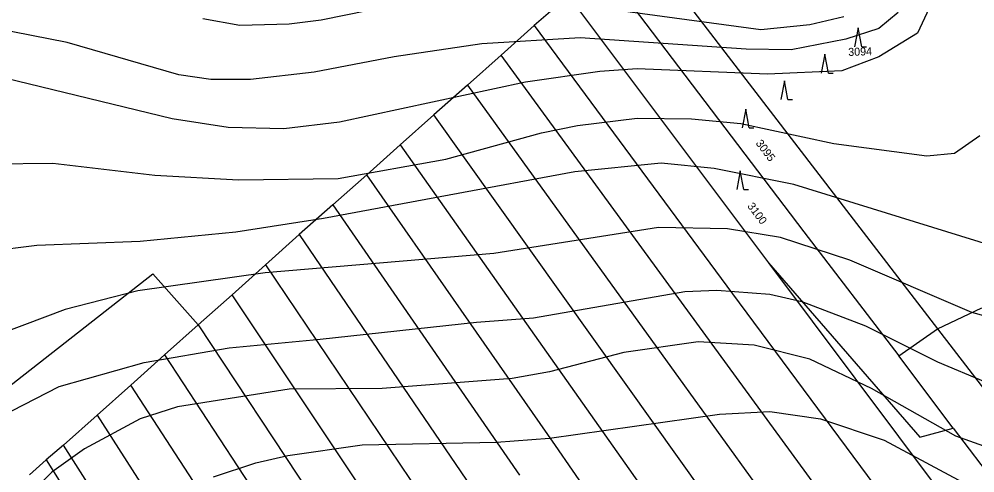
# Model space of a CAD drawing. Extents: x -555860 to -552701, y -1187050 to -1182291.
# Drawn here: x -554858.4 to -554655.3, y -1183272.5 to -1183176.1 of the extents above; entities that cross this region are included whole.
import ezdxf

# ---------------------------------------------------------------- set-up
doc = ezdxf.new("R2010")
doc.units = 0
for name, color, linetype in [('LEG_2b', 7, 'Continuous'), ('Level 25', 7, 'Continuous'), ('Level 40', 7, 'Continuous'), ('Level 41', 7, 'Continuous'), ('navrh_BV', 7, 'Continuous')]:
    doc.layers.add(name, color=color, linetype=linetype)

msp = doc.modelspace()

# ---------------------------------------------------------------- linework, layer by layer
at = {"layer": 'Level 25'}
for p, q in [((-554680.11, -1183177.92), (-554680.86, -1183181.92)), ((-554679.36, -1183181.92), (-554680.11, -1183177.92)), ((-554679.36, -1183181.92), (-554678.36, -1183181.92)), ((-554687.19, -1183183.54), (-554687.94, -1183187.54)), ((-554686.44, -1183187.54), (-554687.19, -1183183.54)), ((-554686.44, -1183187.54), (-554685.44, -1183187.54)), ((-554695.79, -1183189.16), (-554696.54, -1183193.16)), ((-554695.04, -1183193.16), (-554695.79, -1183189.16)), ((-554695.04, -1183193.16), (-554694.04, -1183193.16)), ((-554703.99, -1183195.2), (-554704.74, -1183199.2)), ((-554703.24, -1183199.2), (-554703.99, -1183195.2)), ((-554703.24, -1183199.2), (-554702.24, -1183199.2)), ((-554705.17, -1183208.29), (-554705.92, -1183212.29)), ((-554704.42, -1183212.29), (-554705.17, -1183208.29)), ((-554704.42, -1183212.29), (-554703.42, -1183212.29))]:
    msp.add_line(p, q, dxfattribs=at)
at = {"layer": 'Level 40'}
for points in [[(-554663.14, -1183169.58), (-554667.51, -1183179.03), (-554675.7, -1183184.11), (-554683.6, -1183187.08), (-554699.4, -1183187.78), (-554727.06, -1183186.66), (-554734.96, -1183187.22), (-554750.77, -1183189.48), (-554790.28, -1183197.95), (-554802.14, -1183199.36), (-554813.99, -1183199.07), (-554825.84, -1183197.24), (-554861.41, -1183188.63)], [(-554601.53, -1183237.95), (-554601.47, -1183248.61), (-554602.74, -1183253.4), (-554605.84, -1183258.06), (-554610.22, -1183261.73), (-554618.69, -1183265.26), (-554631.39, -1183267.23), (-554643.52, -1183268.22), (-554651.42, -1183267.52), (-554659.33, -1183264.69), (-554677.25, -1183254.53), (-554690.37, -1183248.32), (-554702.23, -1183245.36), (-554714.08, -1183244.65), (-554729.89, -1183246.91), (-554745.69, -1183251), (-554753.59, -1183252.41), (-554781.25, -1183254.53), (-554801.01, -1183254.67), (-554824.71, -1183258.48), (-554832.62, -1183261.02), (-554844.47, -1183267.37), (-554851.39, -1183272.31), (-554856.75, -1183277.68)]]:
    msp.add_lwpolyline(points, dxfattribs=at)
at = {"layer": 'Level 41'}
for points in [[(-554819.35, -1183175.93), (-554811.45, -1183177.34), (-554801.01, -1183177.06), (-554794.23, -1183176.21), (-554769.4, -1183171.13)], [(-554744.28, -1183172.4), (-554700.8, -1183178.29), (-554690.37, -1183177.2), (-554683.18, -1183175.51)], [(-554671.6, -1183174.66), (-554675.7, -1183178.05), (-554682.75, -1183180.3), (-554694.32, -1183182.56), (-554703.92, -1183182.42), (-554739.2, -1183180.02), (-554760.08, -1183181.29), (-554778.71, -1183184.11), (-554795.65, -1183187.36), (-554809.19, -1183188.91), (-554817.66, -1183188.91), (-554824.43, -1183187.93), (-554848.14, -1183181.01), (-554863.38, -1183178.05)], [(-554925.98, -1183271.71), (-554923.23, -1183261.59), (-554916.72, -1183245.5), (-554913.19, -1183238.73), (-554905.29, -1183228), (-554896.97, -1183219.82), (-554891.04, -1183215.44), (-554886.52, -1183213.04), (-554876.65, -1183209.23), (-554863.95, -1183206.83), (-554851.24, -1183206.69), (-554829.51, -1183209.23), (-554811.73, -1183210.22), (-554790.57, -1183209.94), (-554767.7, -1183205.85), (-554747.38, -1183200.2), (-554739.76, -1183198.65), (-554727.06, -1183197.1), (-554715.49, -1183197.24), (-554705.05, -1183198.23), (-554685.29, -1183202.46), (-554665.54, -1183205.14), (-554659.61, -1183204.58), (-554654.25, -1183200.77)], [(-554651.42, -1183224.33), (-554693.76, -1183211.21), (-554710.69, -1183207.82), (-554721.98, -1183206.69), (-554740.33, -1183208.53), (-554793.67, -1183218.41), (-554812.3, -1183221.37), (-554832.62, -1183223.34), (-554854.63, -1183224.19), (-554864.79, -1183225.46), (-554873.26, -1183227.58), (-554884.97, -1183233.54), (-554892.45, -1183239.71), (-554898.52, -1183245.64), (-554907.13, -1183256.51), (-554914.75, -1183274.57)], [(-554644.65, -1183241.55), (-554655.94, -1183238.44), (-554681.91, -1183227.3), (-554696.58, -1183222.5), (-554707.87, -1183220.66), (-554722.55, -1183220.38), (-554757.54, -1183225.89), (-554806.09, -1183229.98), (-554833.18, -1183233.79), (-554848.56, -1183237.74), (-554866.48, -1183244.51), (-554878.06, -1183250.86), (-554883.7, -1183255.24), (-554891.89, -1183264.13), (-554894.71, -1183268.5), (-554897.81, -1183274.85)], [(-554880.45, -1183277.39), (-554872.13, -1183267.37), (-554862.39, -1183260.6), (-554849.83, -1183254.11), (-554831.77, -1183249.03), (-554813.71, -1183245.92), (-554794.39, -1183244.11), (-554761.23, -1183240.43), (-554749.08, -1183239.57), (-554716.9, -1183233.93), (-554710.13, -1183233.65), (-554698.84, -1183234.49), (-554692.07, -1183236.05), (-554678.52, -1183241.27), (-554663.28, -1183248.89), (-554653.12, -1183253.12)], [(-554817.09, -1183273.3), (-554808.06, -1183270.34), (-554801.29, -1183268.78), (-554785.48, -1183266.53), (-554756.98, -1183265.96), (-554745.69, -1183265.11), (-554709.56, -1183260.03), (-554698.84, -1183259.47), (-554688.11, -1183261.02), (-554674.57, -1183265.54), (-554655.94, -1183275.56)]]:
    msp.add_lwpolyline(points, dxfattribs=at)
at = {"layer": 'navrh_BV'}
for p, q in [((-554727.44, -1183158.26), (-554683.98, -1183214.88)), ((-554734.57, -1183164.68), (-554691.68, -1183221.3)), ((-554741.66, -1183171.12), (-554748.95, -1183177.43)), ((-554741.66, -1183171.12), (-554699.17, -1183227.83)), ((-554748.95, -1183177.43), (-554755.99, -1183183.75)), ((-554748.95, -1183177.43), (-554706.81, -1183234.42)), ((-554755.99, -1183183.75), (-554763.1, -1183190.08)), ((-554714.38, -1183240.66), (-554755.99, -1183183.75)), ((-554763.1, -1183190.08), (-554770.25, -1183196.43)), ((-554763.1, -1183190.08), (-554721.94, -1183247.14)), ((-554770.25, -1183196.43), (-554777.42, -1183202.78)), ((-554729.42, -1183253.68), (-554770.25, -1183196.43)), ((-554777.42, -1183202.78), (-554784.53, -1183209.17)), ((-554777.42, -1183202.78), (-554736.98, -1183260.08)), ((-554784.53, -1183209.17), (-554791.73, -1183215.56)), ((-554744.44, -1183266.69), (-554784.53, -1183209.17)), ((-554683.98, -1183214.88), (-554663.25, -1183241.85)), ((-554791.73, -1183215.56), (-554798.88, -1183221.86)), ((-554791.73, -1183215.56), (-554752.08, -1183272.98)), ((-554691.68, -1183221.3), (-554671.5, -1183247.6)), ((-554798.88, -1183221.86), (-554806.02, -1183228.28)), ((-554798.88, -1183221.86), (-554759.61, -1183279.45)), ((-554806.02, -1183228.28), (-554813.12, -1183234.65)), ((-554806.02, -1183228.28), (-554740.27, -1183325.88)), ((-554699.17, -1183227.83), (-554667.03, -1183264.88)), ((-554699.17, -1183227.83), (-554647, -1183297.46)), ((-554882.99, -1183271.66), (-554829.96, -1183230.22)), ((-554829.96, -1183230.22), (-554820.36, -1183241.01)), ((-554813.12, -1183234.65), (-554820.36, -1183241.01)), ((-554747.72, -1183332.65), (-554813.12, -1183234.65)), ((-554706.81, -1183234.42), (-554654.44, -1183304.99)), ((-554663.25, -1183241.85), (-554653.85, -1183237.43)), ((-554820.36, -1183241.01), (-554827.49, -1183247.43)), ((-554820.36, -1183241.01), (-554755.24, -1183339.43)), ((-554661.89, -1183312.46), (-554714.38, -1183240.66)), ((-554671.5, -1183247.6), (-554663.25, -1183241.85)), ((-554663.25, -1183241.85), (-554632.15, -1183282.48)), ((-554827.49, -1183247.43), (-554834.63, -1183253.83)), ((-554827.49, -1183247.43), (-554762.66, -1183346.26)), ((-554721.94, -1183247.14), (-554669.45, -1183319.88)), ((-554659.9, -1183262.96), (-554671.5, -1183247.6)), ((-554834.63, -1183253.83), (-554841.79, -1183260.25)), ((-554770.2, -1183353.03), (-554834.63, -1183253.83)), ((-554676.87, -1183327.36), (-554729.42, -1183253.68)), ((-554736.98, -1183260.08), (-554684.23, -1183334.91)), ((-554841.79, -1183260.25), (-554848.95, -1183266.59)), ((-554841.79, -1183260.25), (-554777.71, -1183359.82)), ((-554667.03, -1183264.88), (-554659.9, -1183262.96)), ((-554659.9, -1183262.96), (-554639.51, -1183289.98)), ((-554848.95, -1183266.59), (-554852.59, -1183269.75)), ((-554785.23, -1183366.56), (-554848.95, -1183266.59)), ((-554691.66, -1183342.26), (-554744.44, -1183266.69)), ((-554852.59, -1183269.75), (-554856.15, -1183272.92)), ((-554852.59, -1183269.75), (-554789, -1183370.03))]:
    msp.add_line(p, q, dxfattribs=at)

# ---------------------------------------------------------------- texts
at = {"layer": 'LEG_2b'}
for s, rotation, p in [('3094', 2, (-554682.19, -1183183.9)), ('3095', 307, (-554701.97, -1183202.46)), ('3100', 307, (-554703.74, -1183215.82))]:
    msp.add_text(s, height=1.7, rotation=rotation, dxfattribs=at).set_placement(p)

doc.saveas('drawing.dxf')
